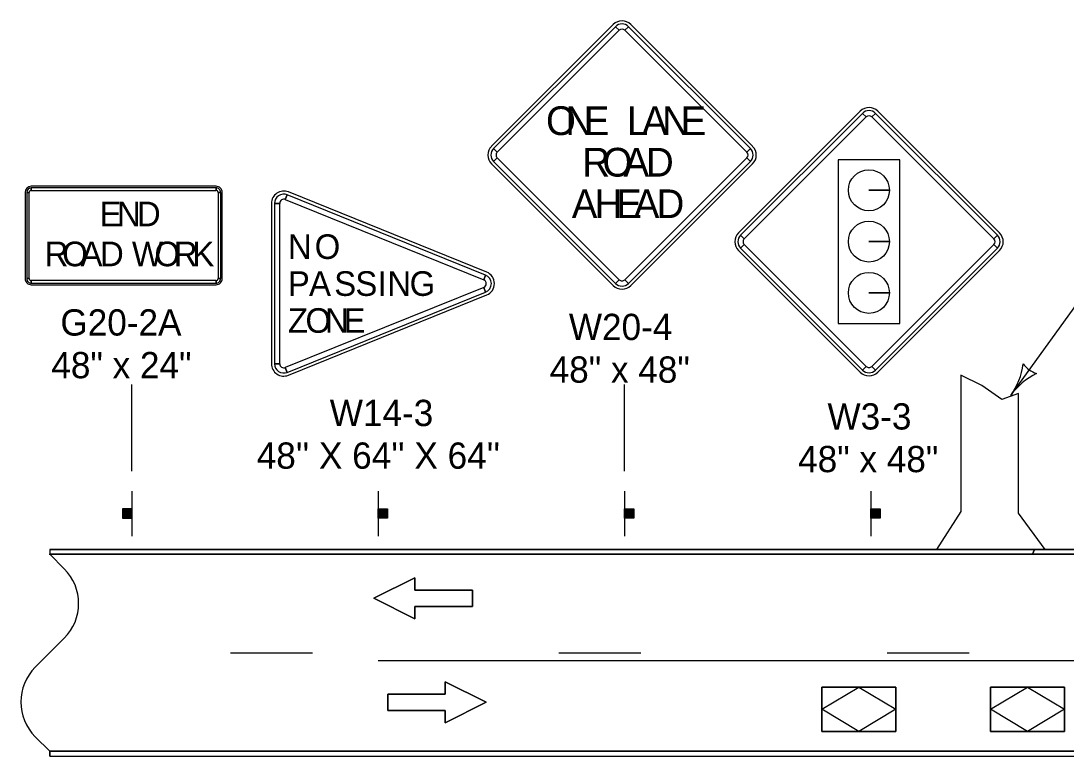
# Model space of a CAD drawing. Extents: x 10124 to 16850, y 7924 to 12166.
# Drawn here: x 13707 to 14343, y 9302 to 9750 of the extents above; entities that cross this region are included whole.
import ezdxf

# ---------------------------------------------------------------- set-up
doc = ezdxf.new("R2010")
doc.units = 0
for name, color, linetype in [('dsnStdLabel', 7, 'Continuous'), ('dsnStdLineWork', 7, 'Continuous'), ('Level 2', 7, 'Continuous'), ('Level 4', 7, 'Continuous')]:
    doc.layers.add(name, color=color, linetype=linetype)

msp = doc.modelspace()

# ---------------------------------------------------------------- linework, layer by layer
at = {"layer": 'dsnStdLabel'}
for p, q in [((14067.51, 9747.63), (13993.26, 9673.39)), ((14068.84, 9746.31), (14071.05, 9744.1)), ((14074.58, 9744.1), (14076.79, 9746.31)), ((14152.36, 9673.39), (14078.12, 9747.63)), ((14217.95, 9694.82), (14143.7, 9620.58)), ((14219.27, 9693.49), (14221.48, 9691.29)), ((14225.02, 9691.29), (14227.23, 9693.49)), ((14302.8, 9620.58), (14228.55, 9694.82)), ((13996.8, 9669.85), (13994.59, 9672.06)), ((14151.04, 9672.06), (14148.83, 9669.85)), ((13994.59, 9664.11), (13996.8, 9666.32)), ((14148.83, 9666.32), (14151.04, 9664.11)), ((13993.26, 9662.78), (14067.51, 9588.54)), ((14078.12, 9588.54), (14152.36, 9662.78)), ((13709.3, 9645.31), (13709.3, 9592.81)), ((13710.24, 9645.31), (13711.8, 9645.31)), ((13825.55, 9649.06), (13713.05, 9649.06)), ((13713.05, 9646.56), (13713.05, 9648.12)), ((13825.55, 9648.12), (13825.55, 9646.56)), ((13826.8, 9645.31), (13828.37, 9645.31)), ((13829.3, 9592.81), (13829.3, 9645.31)), ((13990.45, 9596.7), (13869.62, 9645.58)), ((14235.66, 9646.6), (14223.16, 9646.6)), ((14223.16, 9646.6), (14235.66, 9646.6)), ((13859.31, 9638.62), (13859.31, 9540.87)), ((13861.18, 9638.62), (13864.31, 9638.62)), ((13867.75, 9640.94), (13868.92, 9643.84)), ((14147.24, 9617.04), (14145.03, 9619.25)), ((14301.47, 9619.25), (14299.26, 9617.04)), ((14145.03, 9611.29), (14147.24, 9613.5)), ((14235.66, 9615.35), (14223.16, 9615.35)), ((14223.16, 9615.35), (14235.66, 9615.35)), ((14299.26, 9613.5), (14301.47, 9611.29)), ((14143.7, 9609.97), (14217.95, 9535.72)), ((14228.55, 9535.72), (14302.8, 9609.97)), ((13989.74, 9594.96), (13988.57, 9592.06)), ((13711.8, 9592.81), (13710.24, 9592.81)), ((13713.05, 9590), (13713.05, 9591.56)), ((13713.05, 9589.06), (13825.55, 9589.06)), ((13825.55, 9591.56), (13825.55, 9590)), ((13828.37, 9592.81), (13826.8, 9592.81)), ((13988.57, 9587.43), (13989.74, 9584.53)), ((14071.05, 9592.07), (14068.84, 9589.86)), ((14076.79, 9589.86), (14074.58, 9592.07)), ((13869.62, 9533.92), (13990.45, 9582.79)), ((14235.66, 9584.1), (14223.16, 9584.1)), ((14223.16, 9584.1), (14235.66, 9584.1)), ((13864.31, 9540.87), (13861.18, 9540.87)), ((13868.92, 9535.66), (13867.75, 9538.55)), ((14221.48, 9539.26), (14219.27, 9537.05)), ((14227.23, 9537.05), (14225.02, 9539.26))]:
    msp.add_line(p, q, dxfattribs=at)
for points in [[(14068.84, 9746.31), (13994.59, 9672.06), (13996.8, 9669.85), (14071.05, 9744.1), (14068.84, 9746.31)], [(14151.04, 9672.06), (14076.79, 9746.31), (14074.58, 9744.1), (14148.83, 9669.85), (14151.04, 9672.06)], [(14219.27, 9693.49), (14145.03, 9619.25), (14147.24, 9617.04), (14221.48, 9691.29), (14219.27, 9693.49)], [(14301.47, 9619.25), (14227.23, 9693.49), (14225.02, 9691.29), (14299.26, 9617.04), (14301.47, 9619.25)], [(13994.59, 9664.11), (14068.84, 9589.86), (14071.05, 9592.07), (13996.8, 9666.32), (13994.59, 9664.11)], [(14076.79, 9589.86), (14151.04, 9664.11), (14148.83, 9666.32), (14074.58, 9592.07), (14076.79, 9589.86)], [(14241.98, 9665.22), (14204.52, 9665.22), (14204.52, 9565.33), (14241.98, 9565.33), (14241.98, 9665.22)], [(13710.24, 9645.31), (13710.24, 9592.81), (13711.8, 9592.81), (13711.8, 9645.31), (13710.24, 9645.31)], [(13825.55, 9648.12), (13713.05, 9648.12), (13713.05, 9646.56), (13825.55, 9646.56), (13825.55, 9648.12)], [(13828.37, 9592.81), (13828.37, 9645.31), (13826.8, 9645.31), (13826.8, 9592.81), (13828.37, 9592.81)], [(13861.18, 9638.62), (13861.18, 9540.87), (13864.31, 9540.87), (13864.31, 9638.62), (13861.18, 9638.62)], [(13989.74, 9594.96), (13868.92, 9643.84), (13867.75, 9640.94), (13988.57, 9592.06), (13989.74, 9594.96)], [(14145.03, 9611.29), (14219.27, 9537.05), (14221.48, 9539.26), (14147.24, 9613.5), (14145.03, 9611.29)], [(14227.23, 9537.05), (14301.47, 9611.29), (14299.26, 9613.5), (14225.02, 9539.26), (14227.23, 9537.05)], [(13713.05, 9590), (13825.55, 9590), (13825.55, 9591.56), (13713.05, 9591.56), (13713.05, 9590)], [(13868.92, 9535.66), (13989.74, 9584.53), (13988.57, 9587.43), (13867.75, 9538.55), (13868.92, 9535.66)]]:
    msp.add_lwpolyline(points, close=True, dxfattribs=at)
for centre in [(14223.16, 9646.6), (14223.16, 9615.35), (14223.16, 9584.1)]:
    msp.add_circle(centre, 12.5, dxfattribs=at)
for centre, radius, start, end in [((14072.81, 9742.33), 7.5, 44.99999, 134.99974), ((14072.81, 9742.33), 5.62, 44.99999, 134.99974), ((14072.81, 9742.33), 2.5, 44.99999, 134.99974), ((14223.25, 9689.52), 7.5, 44.99999, 134.99974), ((14223.25, 9689.52), 5.62, 44.99999, 134.99974), ((14223.25, 9689.52), 2.5, 44.99999, 134.99974), ((13998.57, 9668.08), 7.5, 134.99974, 224.99995), ((13998.57, 9668.08), 5.62, 134.99974, 224.99995), ((13998.57, 9668.08), 2.5, 134.99974, 224.99995), ((14147.06, 9668.08), 2.5, 315.00016, 44.9998), ((14147.06, 9668.08), 5.62, 315.00016, 44.9998), ((14147.06, 9668.08), 7.5, 315.00016, 44.9998), ((13713.05, 9645.31), 3.75, 90.00021, 179.99985), ((13713.05, 9645.31), 2.81, 90.00021, 179.99985), ((13713.05, 9645.31), 1.25, 90.00021, 179.99985), ((13825.55, 9645.31), 3.75, 0, 90.00021), ((13825.55, 9645.31), 2.81, 0, 90.00021), ((13825.55, 9645.31), 1.25, 0, 90.00021), ((13866.81, 9638.62), 7.5, 67.97571, 179.99985), ((13866.81, 9638.62), 5.62, 67.97571, 179.99985), ((13866.81, 9638.62), 2.5, 67.97571, 179.99985), ((14149, 9615.27), 7.5, 134.99974, 224.99995), ((14149, 9615.27), 5.62, 134.99974, 224.99995), ((14297.49, 9615.27), 5.62, 315.00016, 44.9998), ((14297.49, 9615.27), 7.5, 315.00016, 44.9998), ((14149, 9615.27), 2.5, 134.99974, 224.99995), ((14297.49, 9615.27), 2.5, 315.00016, 44.9998), ((13987.63, 9589.75), 5.62, 292.02456, 67.97541), ((13987.63, 9589.75), 7.5, 292.02456, 67.97598), ((13713.05, 9592.81), 3.75, 179.99985, 270.00006), ((13713.05, 9592.81), 2.81, 179.99985, 270.00006), ((13713.05, 9592.81), 1.25, 179.99985, 270.00006), ((13825.55, 9592.81), 3.75, 270.00006, 0.00027), ((13825.55, 9592.81), 2.81, 270.00006, 0.00027), ((13825.55, 9592.81), 1.25, 270.00006, 0.00027), ((13987.63, 9589.75), 2.5, 292.02456, 67.97541), ((14072.81, 9593.84), 7.5, 224.99995, 315.00016), ((14072.81, 9593.84), 5.62, 224.99995, 315.00016), ((14072.81, 9593.84), 2.5, 224.99995, 315.00016), ((13866.81, 9540.87), 7.5, 179.99985, 292.02456), ((13866.81, 9540.87), 5.62, 179.99985, 292.02456), ((13866.81, 9540.87), 2.5, 179.99985, 292.02456), ((14223.25, 9541.03), 5.62, 224.99995, 315.00016), ((14223.25, 9541.03), 2.5, 224.99995, 315.00016), ((14223.25, 9541.03), 7.5, 224.99995, 315.00016)]:
    msp.add_arc(centre, radius, start, end, dxfattribs=at)
at = {"layer": 'dsnStdLineWork'}
for p, q in [((14291.91, 9527.71), (14279.22, 9533.88)), ((14279.22, 9533.88), (14279.22, 9450.9)), ((14304.18, 9519.1), (14291.91, 9527.71)), ((14314.21, 9522.86), (14304.18, 9519.1)), ((14314.21, 9449.75), (14314.21, 9522.86)), ((14279.22, 9450.9), (14264.28, 9427.79)), ((14330.52, 9427.79), (14314.21, 9449.75)), ((13724.28, 9427.79), (13724.28, 9424.79)), ((13724.28, 9427.79), (13724.28, 9424.79)), ((14324.05, 9427.79), (13724.28, 9427.79)), ((14264.28, 9427.79), (14330.52, 9427.79)), ((14324.05, 9427.79), (14322.86, 9424.79)), ((14322.86, 9424.79), (14324.05, 9427.79)), ((14369.28, 9427.79), (14324.05, 9427.79)), ((13724.28, 9424.79), (14322.86, 9424.79)), ((14322.86, 9424.79), (14369.28, 9424.79)), ((13834.28, 9364.79), (13884.28, 9364.79)), ((14034.28, 9364.79), (14034.28, 9364.79)), ((14034.28, 9364.79), (14084.28, 9364.79)), ((14234.28, 9364.79), (14234.28, 9364.79)), ((14234.28, 9364.79), (14284.28, 9364.79)), ((14374.28, 9359.79), (13924.28, 9359.79)), ((13724.28, 9304.79), (15224.27, 9304.79)), ((13724.28, 9304.79), (15224.27, 9304.79)), ((13724.28, 9301.79), (13724.28, 9304.79)), ((14369.28, 9304.79), (13724.28, 9304.79)), ((13724.28, 9304.79), (13724.28, 9301.79)), ((13724.28, 9301.79), (15224.27, 9301.79)), ((13724.28, 9301.79), (15224.27, 9301.79))]:
    msp.add_line(p, q, dxfattribs=at)
for points in [[(13724.28, 9427.79), (15034.28, 9427.79)], [(13723.86, 9424.79), (15033.86, 9424.79)], [(13724.28, 9424.79), (15034.28, 9424.79)]]:
    msp.add_lwpolyline(points, dxfattribs=at)
at = {"layer": 'Level 2'}
for p, q in [((14309.54, 9521.63), (14361.76, 9593.87)), ((13774.28, 9475.45), (13774.28, 9528.32)), ((14074.28, 9475.45), (14074.28, 9528.32)), ((13774.28, 9463.29), (13774.28, 9435.79)), ((13924.28, 9463.29), (13924.28, 9435.79)), ((14074.28, 9463.29), (14074.28, 9435.79)), ((14224.28, 9463.29), (14224.28, 9435.79)), ((13768.95, 9452.42), (13768.95, 9446.84)), ((13769.27, 9446.84), (13769.27, 9452.42)), ((13769.5, 9452.42), (13769.5, 9446.84)), ((13769.81, 9446.84), (13769.81, 9452.42)), ((13770.04, 9452.42), (13770.02, 9446.84)), ((13770.45, 9446.84), (13770.47, 9452.42)), ((13770.68, 9452.42), (13770.68, 9446.84)), ((13771.11, 9446.84), (13771.11, 9452.42)), ((13771.48, 9452.42), (13771.48, 9446.84)), ((13771.8, 9446.84), (13771.82, 9452.42)), ((13772.03, 9452.42), (13772.03, 9446.84)), ((13772.29, 9446.84), (13772.29, 9452.42)), ((13772.63, 9452.42), (13772.63, 9446.84)), ((13772.83, 9446.84), (13772.83, 9452.42)), ((13773.06, 9452.42), (13773.06, 9446.84)), ((13773.32, 9446.84), (13773.32, 9452.42)), ((13773.58, 9452.42), (13773.58, 9446.84)), ((13773.86, 9446.84), (13773.86, 9452.42)), ((13924.69, 9446.84), (13924.69, 9452.42)), ((13924.97, 9452.42), (13924.97, 9446.84)), ((13925.23, 9446.84), (13925.23, 9452.42)), ((13925.5, 9452.42), (13925.5, 9446.84)), ((13925.72, 9446.84), (13925.72, 9452.42)), ((13925.93, 9452.42), (13925.93, 9446.84)), ((13926.27, 9446.84), (13926.27, 9452.42)), ((13926.53, 9452.42), (13926.53, 9446.84)), ((13926.75, 9446.84), (13926.73, 9452.42)), ((13927.07, 9452.42), (13927.07, 9446.84)), ((13927.45, 9446.84), (13927.45, 9452.42)), ((13927.88, 9452.42), (13927.88, 9446.84)), ((13928.1, 9446.84), (13928.08, 9452.42)), ((13928.52, 9452.42), (13928.53, 9446.84)), ((13928.74, 9446.84), (13928.74, 9452.42)), ((13929.06, 9452.42), (13929.06, 9446.84)), ((13929.28, 9446.84), (13929.28, 9452.42)), ((13929.6, 9452.42), (13929.6, 9446.84)), ((14074.69, 9446.84), (14074.69, 9452.42)), ((14074.97, 9452.42), (14074.97, 9446.84)), ((14075.23, 9446.84), (14075.23, 9452.42)), ((14075.5, 9452.42), (14075.5, 9446.84)), ((14075.72, 9446.84), (14075.72, 9452.42)), ((14075.93, 9452.42), (14075.93, 9446.84)), ((14076.27, 9446.84), (14076.27, 9452.42)), ((14076.53, 9452.42), (14076.53, 9446.84)), ((14076.75, 9446.84), (14076.73, 9452.42)), ((14077.07, 9452.42), (14077.07, 9446.84)), ((14077.45, 9446.84), (14077.45, 9452.42)), ((14077.88, 9452.42), (14077.88, 9446.84)), ((14078.1, 9446.84), (14078.08, 9452.42)), ((14078.52, 9452.42), (14078.53, 9446.84)), ((14078.74, 9446.84), (14078.74, 9452.42)), ((14079.06, 9452.42), (14079.06, 9446.84)), ((14079.28, 9446.84), (14079.28, 9452.42)), ((14079.6, 9452.42), (14079.6, 9446.84)), ((14224.69, 9446.84), (14224.69, 9452.42)), ((14224.97, 9452.42), (14224.97, 9446.84)), ((14225.23, 9446.84), (14225.23, 9452.42)), ((14225.5, 9452.42), (14225.5, 9446.84)), ((14225.72, 9446.84), (14225.72, 9452.42)), ((14225.93, 9452.42), (14225.93, 9446.84)), ((14226.26, 9446.84), (14226.26, 9452.42)), ((14226.53, 9452.42), (14226.53, 9446.84)), ((14226.75, 9446.84), (14226.73, 9452.42)), ((14227.07, 9452.42), (14227.07, 9446.84)), ((14227.45, 9446.84), (14227.45, 9452.42)), ((14227.88, 9452.42), (14227.88, 9446.84)), ((14228.1, 9446.84), (14228.08, 9452.42)), ((14228.52, 9452.42), (14228.53, 9446.84)), ((14228.74, 9446.84), (14228.74, 9452.42)), ((14229.06, 9452.42), (14229.06, 9446.84)), ((14229.28, 9446.84), (14229.28, 9452.42)), ((14229.6, 9452.42), (14229.6, 9446.84)), ((13733.06, 9416), (13724.28, 9424.79)), ((15034.28, 9424.79), (13724.28, 9424.79)), ((13724.28, 9424.79), (13733.06, 9416)), ((13715.49, 9356), (13733.06, 9373.57)), ((13733.06, 9373.57), (13715.49, 9356)), ((14194.6, 9316.82), (14194.6, 9343.82)), ((14194.6, 9343.82), (14239.6, 9343.82)), ((14194.6, 9316.82), (14194.6, 9343.82)), ((14194.6, 9343.82), (14239.6, 9343.82)), ((14239.6, 9343.82), (14194.6, 9343.82)), ((14194.6, 9343.82), (14194.6, 9316.82)), ((14239.6, 9316.82), (14239.6, 9343.82)), ((14239.6, 9343.82), (14239.6, 9316.82)), ((14239.6, 9316.82), (14239.6, 9343.82)), ((14297.28, 9316.82), (14297.28, 9343.82)), ((14297.28, 9343.82), (14342.28, 9343.82)), ((14297.28, 9316.82), (14297.28, 9343.82)), ((14297.28, 9343.82), (14342.28, 9343.82)), ((14342.28, 9343.82), (14297.28, 9343.82)), ((14297.28, 9343.82), (14297.28, 9316.82)), ((14342.28, 9316.82), (14342.28, 9343.82)), ((14342.28, 9343.82), (14342.28, 9316.82)), ((14342.28, 9316.82), (14342.28, 9343.82)), ((13724.28, 9304.79), (13715.49, 9313.57)), ((13715.49, 9313.57), (13724.28, 9304.79)), ((14194.6, 9316.82), (14239.6, 9316.82)), ((14239.6, 9316.82), (14194.6, 9316.82)), ((14194.6, 9316.82), (14239.6, 9316.82)), ((14297.28, 9316.82), (14342.28, 9316.82)), ((14342.28, 9316.82), (14297.28, 9316.82)), ((14297.28, 9316.82), (14342.28, 9316.82)), ((13724.28, 9304.79), (15224.27, 9304.79))]:
    msp.add_line(p, q, dxfattribs=at)
for points in [[(13774.18, 9446.84), (13774.18, 9452.46), (13768.56, 9452.46), (13768.56, 9446.84)], [(13924.37, 9446.84), (13924.37, 9452.46), (13930, 9452.46), (13930, 9446.84)], [(14074.37, 9446.84), (14074.37, 9452.46), (14080, 9452.46), (14080, 9446.84)], [(14224.37, 9446.84), (14224.37, 9452.46), (14230, 9452.46), (14230, 9446.84)], [(13981.68, 9392.95), (13981.68, 9402.95), (13946.68, 9402.95), (13946.68, 9410.45), (13921.68, 9397.95), (13946.68, 9385.45), (13946.68, 9392.95)], [(13930.17, 9339.61), (13930.17, 9329.61), (13965.17, 9329.61), (13965.17, 9322.11), (13990.17, 9334.61), (13965.17, 9347.11), (13965.17, 9339.61)]]:
    msp.add_lwpolyline(points, close=True, dxfattribs=at)
for points in [[(13946.68, 9392.95), (13946.68, 9385.45), (13921.68, 9397.95), (13946.68, 9410.45), (13946.68, 9402.95), (13981.68, 9402.95), (13981.68, 9392.95), (13946.68, 9392.95)], [(13965.17, 9339.61), (13965.17, 9347.11), (13990.17, 9334.61), (13965.17, 9322.11), (13965.17, 9329.61), (13930.17, 9329.61), (13930.17, 9339.61), (13965.17, 9339.61)]]:
    msp.add_lwpolyline(points, dxfattribs=at)
for centre, radius, start, end in [((14275.09, 9546.52), 42.5, 324.13796, 352.21045), ((14330.41, 9550.51), 16.42, 216.40461, 251.87131), ((14343.98, 9496.73), 42.5, 116.06547, 144.13796), ((13711.85, 9394.79), 30, 315, 45), ((13711.85, 9394.79), 30, 315, 45), ((13736.7, 9334.79), 30, 135, 225), ((13736.7, 9334.79), 30, 135, 225)]:
    msp.add_arc(centre, radius, start, end, dxfattribs=at)
at = {"layer": 'Level 4'}
for points in [[(14194.6, 9330.32), (14217.1, 9343.82), (14239.6, 9330.32), (14217.1, 9316.82)], [(14297.28, 9330.32), (14319.78, 9343.82), (14342.28, 9330.32), (14319.78, 9316.82)]]:
    msp.add_lwpolyline(points, close=True, dxfattribs=at)

# ---------------------------------------------------------------- texts
at = {"layer": 'dsnStdLabel'}
for s, height, p in [('O', 17.5, (14026.53, 9680.27)), ('N', 17.5, (14038.3, 9680.27)), ('E', 17.5, (14049.53, 9680.27)), ('L', 17.5, (14075.78, 9680.27)), ('A', 17.5, (14084.98, 9680.27)), ('N', 17.5, (14097.25, 9680.27)), ('E', 17.5, (14108.47, 9680.27)), ('R', 17.5, (14048.64, 9654.96)), ('O', 17.5, (14060.93, 9654.96)), ('A', 17.5, (14073.76, 9654.96)), ('D', 17.5, (14087.42, 9654.96)), ('A', 17.5, (14042.2, 9629.65)), ('H', 17.5, (14056.06, 9629.65)), ('E', 17.5, (14069.28, 9629.65)), ('A', 17.5, (14079.99, 9629.65)), ('D', 17.5, (14093.86, 9629.65)), ('E', 15, (13754.63, 9624.68)), ('N', 15, (13765.25, 9624.68)), ('D', 15, (13777.34, 9624.68)), ('N', 15, (13869.28, 9604.75)), ('O', 15, (13885.62, 9604.75)), ('R', 15, (13721.17, 9600.31)), ('O', 15, (13731.85, 9600.31)), ('A', 15, (13743.01, 9600.31)), ('D', 15, (13754.86, 9600.31)), ('W', 15, (13774.32, 9600.31)), ('O', 15, (13788.05, 9600.31)), ('R', 15, (13799.82, 9600.31)), ('K', 15, (13811.11, 9600.31)), ('P', 15, (13869.28, 9582.25)), ('A', 15, (13882.17, 9582.25)), ('S', 15, (13897.52, 9582.25)), ('S', 15, (13910.41, 9582.25)), ('I', 15, (13924.01, 9582.25)), ('N', 15, (13929.87, 9582.25)), ('G', 15, (13943.46, 9582.25)), ('Z', 15, (13869.28, 9559.75)), ('O', 15, (13880.01, 9559.75)), ('N', 15, (13891.85, 9559.75)), ('E', 15, (13903.21, 9559.75))]:
    msp.add_text(s, height=height, dxfattribs=at).set_placement(p)
at = {"layer": 'Level 2'}
for s, p in [('G20-2A', (13730.77, 9558.06)), ('W20-4', (14040.45, 9555.34)), ('48" x 24"', (13725.24, 9532.06)), ('48" x 48"', (14028.75, 9529.34)), ('W14-3', (13894.82, 9502.92)), ('W3-3', (14197.96, 9500.81)), ("48'' X 64'' X 64''", (13850.33, 9476.92)), ('48" x 48"', (14180.08, 9474.81))]:
    msp.add_text(s, height=16, dxfattribs=at).set_placement(p)

doc.saveas('drawing.dxf')
